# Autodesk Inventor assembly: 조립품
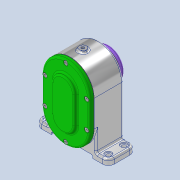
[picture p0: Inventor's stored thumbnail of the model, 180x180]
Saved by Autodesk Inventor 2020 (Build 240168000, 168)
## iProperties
Created: 2021-05
Part Number: 조립품
Document SubType Name: Assembly
Designer: Owner
Author: Owner
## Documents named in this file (19)
- C:\Users\Owner\Desktop\710507V1012\조립품.iam
- C:\Users\Owner\Desktop\710507V1012\1. 본체.ipt
- C:\Users\Owner\Desktop\710507V1012\축 A.ipt
- C:\Users\Owner\Desktop\710507V1012\베어링 6001.ipt
- 베어링 6001.ipt
- C:\Users\Owner\Desktop\710507V1012\축 B.ipt
- C:\Users\Owner\Desktop\710507V1012\베어링 6002.ipt
- 베어링 6002.ipt
- C:\Users\Owner\Desktop\710507V1012\칼라.ipt
- C:\Users\Owner\Desktop\710507V1012\키 5 x 5 x 12.ipt
- C:\Users\Owner\Desktop\710507V1012\키 4 x 4 x 12.ipt
- C:\Users\Owner\Desktop\710507V1012\커버 A.ipt
- C:\Users\Owner\Desktop\710507V1012\스퍼기어 A.ipt
- C:\Users\Owner\Desktop\710507V1012\스퍼기어 B.ipt
- C:\Users\Owner\Desktop\710507V1012\커버 B.ipt
- C:\Users\Owner\Desktop\710507V1012\오일 실 12 22 7.ipt
- C:\Users\Owner\Desktop\710507V1012\개스킷 A.ipt
- C:\Users\Owner\Desktop\710507V1012\개스킷 B.ipt
- C:\Users\Owner\Desktop\710507V1012\볼트 M4.ipt
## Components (3 placed, 3 different names)
1. 1. 본체:1
2. 개스킷 A:1
3. 개스킷 B:1
